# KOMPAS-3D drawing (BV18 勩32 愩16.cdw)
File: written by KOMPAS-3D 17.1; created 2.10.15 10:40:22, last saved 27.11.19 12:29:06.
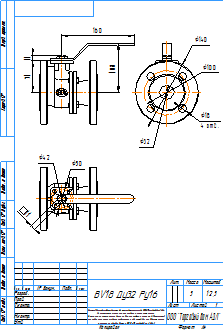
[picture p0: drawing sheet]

Sheet 1: A4, portrait

Title block, sheet 1: name: BV18 Ду32 Ру16; material: Сталь 10  ГОСТ 1050-88; mass: 5; sheets: 1; sheet format: A4; stored path: C:\Users\kka\KOMPAS_Work\!Trash\BV18\KOMPAS 2D\BV18 Ду100 Ру16 с голым штоком.cdw

Views: Спереди 4, Проекционный вид 6
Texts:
  Klimkovich
  ADL
  Рама для чертежей
  Лит-Масса-Масштаб
  Материал-Предприятие
  Масштаб
  Изм.
  Лист
  № докум.
  Подп.
  Дата
  Лит.
  Разраб.
  Пров.
  Т.контр.
  Листов
  Внимание! Данный продукт является объектом авторского права ООО «Торговый Дом АДЛ».
  Запрещается изменение, копирование, распространение
  (в том числе путем копирования на другие сайты и ресурсы в Интернете)
  или любое иное использование информации и объектов без предварительного
  согласия правообладателя (ООО «Торговый Дом АДЛ»).
  Н.контр.
  Утв.
  ООО "Торговый дом АДЛ"
  Изменение
  Номер документа
  Подпись
  Обозначение документа
  Наименование изделия
  Масса изделия по ГОСТ 2.109-73
  Порядковый номер листа
  Общее количество листов в документе
  Характер работы, выполненной лицом, подписавшим документ
  Наименование или индекс предприятия, выпускающего документ
  Инв. № подл.
  Подп. и дата
  Взам. инв. №
  Инв. № дубл.
  Инвентарный номер подлинника по ГОСТ 2.501-68
  Подпись принявшего подлинник в отдел технической документации
  Инвентарный номер подлинника, взамен которого выпущен данный подлинник
  Инвентарный номер дубликата по ГОСТ 2.502-68
  Подпись принявшего дубликат в отдел технической документации
  Справ. №
  Перв. примен.
  Обозначение документа, взамен или на основании которого выпущен данный документ
  Обозначение документа, в котором впервые записан данный документ
  Подпись лица, копировавшего чертеж
  Обозначение формата листа
  !Рама для чертежа
Dimensions and other numbers on the sheet: 11; 71; 160; 108; 140; 100; 18; 4 отв.; 32; 1:2,5; 1; 5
